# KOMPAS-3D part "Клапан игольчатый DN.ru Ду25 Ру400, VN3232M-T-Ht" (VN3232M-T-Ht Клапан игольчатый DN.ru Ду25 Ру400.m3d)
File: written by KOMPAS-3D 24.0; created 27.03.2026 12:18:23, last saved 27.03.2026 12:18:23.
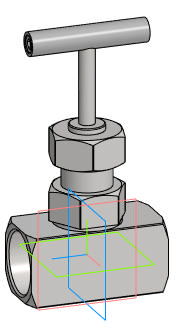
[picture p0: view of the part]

Document properties: Автор: Илья; Полное имя файла: D:\Обмен\Заказы с фриланса\DN.ru\VNxxM-T-Ht Клапан игольчатый DN.ru Ду8-50 Ру400\VN3232M-T-Ht Клапан игольчатый DN.ru Ду8-50 Ру400\DN25\VN3232M-T-Ht Клапан игольчатый DN.ru Ду25 Ру400.m3d

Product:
- Body: Body7  | qty 1
    Масса: 0.81876
- Part/product: Клапан игольчатый DN.ru Ду25 Ру400  | designation VN3232M-T-Ht
    Масса: 0.8
    Раздел спецификации: Прочие изделия
    Примечание: D090-02133

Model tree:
1. Body7  (labels: Body7)

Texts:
  VN3232M-T-Ht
